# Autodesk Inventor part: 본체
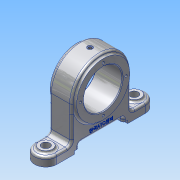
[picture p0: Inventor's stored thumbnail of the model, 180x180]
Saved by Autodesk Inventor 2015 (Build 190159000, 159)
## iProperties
Created: 2019-05
Part Number: 본체
Material: 알루미늄 6061
Document SubType Name: Modeling
Designer: user
Density: 2.7 g/cm^3
Appearance: 알루미늄 - 평지
Mass: 456.014 g
Surface Area: 318.798 cm^2
Volume: 168.894 cm^3
Author: user
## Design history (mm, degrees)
sketch "스케치1" dims "d1" = 80, "d3" = 62
  geometry: L1 (-30, 0)-(110, 0) reference; L2 (50, -40)-(2, -40); L3 (2, -40)-(2, -75); L4 (2, -75)-(-10, -75); L5 (-10, -75)-(-10, -36); L6 (0, -30)-(0, 0); L7 (0, -30)-(-6, -30); L8 (-6, -30)-(-6, -36); L9 (-6, -36)-(-10, -36); L10 (2, 40)-(2, 75); L11 (2, 75)-(-10, 75); L12 (-10, 75)-(-10, 36); L13 (-6, 30)-(-6, 36); L14 (-6, 36)-(-10, 36); L15 (0, 30)-(0, 0); L16 (0, 30)-(-6, 30); L17 (50, 40)-(2, 40); C1 r 26 at (50, 0); A1 r 40 centre (50, 0) between (50, 40) and (50, -40); 4 further points
  constraints: 32 end point, 8 symmetric about line, 4 coincident, 4 horizontal, 3 perpendicular, 2 centre point, 2 horizontal alignment, 2 point on circle, 2 vertical alignment, 1 vertical, 6 other
  dimensions: "d2" = 52 diameter of C1; "d4" = 72 diameter of L9 L1; "d5" = 60 diameter of L7 L1; "d6" = 150 diameter of L4 L1; "d8" = 60 distance from line of L5 point (50, 0); "d9" = 100 dimension on L5 (derived); "d10" = 4 distance of L8.end L5.end; "d11" = 10 distance between parallel lines of L5 L6; "d18" = 12 distance between parallel lines of L5 L3
extrude "돌출1" new body sketch "스케치1" stored distance "d19" = 30; taper "d20" = 0 deg
fillet "모깎기1" dims "d21" = 15
sketch "스케치2"
  geometry: L1 (30, 0)-(30, -20) reference; L2 (0, 0)-(30, 0) reference; L3 (0, -20)-(0, 0) reference; L4 (0, 80)-(0, 100) reference; L5 (0, 80)-(30, 80) reference; L6 (30, 100)-(30, 80) reference; C1 r 9 at (15, -20); A1 r 15 centre (15, -20) between (0, -20) and (30, -20) reference; A2 r 15 centre (15, 100) between (30, 100) and (0, 100) reference; 1 further point
  constraints: 1 centre point, 1 coincident
  dimensions: "d22" = 18 diameter of C1
extrude "돌출2" join sketch "스케치2" distance "d23" = 3; taper "d24" = 0 deg
sketch "스케치3"
  geometry: C1 r 9 at (0, 0) reference; 1 further point
hole "구멍1" sketch "스케치3" at (0, 0) diameter "d25" = 11; stored, may be unused: countersink angle "d29" = 90 deg, drill point angle "d31" = 118 deg; dims "d26" = 6, "d27" = 4, "d28" = 2, "d30" = 8
sketch "스케치4"
  geometry: C1 r 26 at (0, 50) reference; C2 r 36 at (0, 50); 1 further point
  constraints: 1 centre point, 1 coincident
  dimensions: "d32" = 72 diameter of C2
extrude "돌출3" join sketch "스케치4" distance "d33" = 3; taper "d34" = 0 deg
sketch "스케치5"
  geometry: C1 r 26 at (0, 0) reference; C2 r 26 at (0, 0) reference; 2 further points
  constraints: 1 vertical alignment
  dimensions: "d35" = 31 distance of C1.centre point (0, 31)
hole "구멍2" sketch "스케치5" at (0, 31) diameter "d36" = 3.242; stored, may be unused: countersink angle "d40" = 90 deg, drill point angle "d42" = 118 deg; dims "d37" = 6, "d38" = 7, "d39" = 1, "d41" = 8
node "작업 평면1"
sketch "스케치6"
  geometry: 1 further point
hole "구멍3" sketch "스케치6" at (0, 0) diameter "d46" = 4.917; stored, may be unused: countersink angle "d50" = 90 deg, drill point angle "d52" = 118 deg; dims "d47" = 8, "d48" = 7, "d49" = 1, "d51" = 10
node "작업 평면2"
sketch "스케치8"
  geometry: L1 (-30, 0)-(30, 0) reference; 2 further points
  constraints: 1 vertical alignment, 1 other
  dimensions: "d54" = 7 distance from line of L1 point (0, 7)
fillet "모깎기2" dims "d55" = 3
fillet "모깎기3" dims "d56" = 3
fillet "모깎기4" dims "d57" = 3
fillet "모깎기5" dims "d58" = 3
fillet "모깎기6" dims "d59" = 6
fillet "모깎기7" dims "d60" = 6
fillet "모깎기8" dims "d61" = 3
fillet "모깎기9" dims "d62" = 3
fillet "모깎기10" dims "d63" = 3
chamfer "모따기1" distance "d64" = 1; stored, may be unused: second distance "d65" = 2, angle "d66" = 45 deg
sketch "스케치9"
  geometry: C1 r 1 at (0, 0); 1 further point
  constraints: 1 centre point, 1 coincident
  dimensions: "d67" = 2 diameter of C1
extrude "돌출4" cut sketch "스케치9" stored distance "d68" = 3; taper "d69" = 0 deg
feature "엠보싱1" dims "d70" = 0.5, "d71" = 0
sketch "스케치10"
  geometry: C1 r 1.5 at (0, 26); C2 r 1.621 at (0, 31) reference; 2 further points
  constraints: 2 vertical alignment, 1 centre point, 1 other
  dimensions: "d73" = 3 diameter of C1
extrude "돌출5" cut sketch "스케치10" stored distance "d74" = 3; taper "d75" = 0 deg
node "솔리드1"
mirror "대칭1"
pattern_circular "원형 패턴1" dims angle "d44" = 360 deg
mirror "대칭2"
mirror "대칭3"
mirror "대칭4"
node "투영된 루프1"
node "투영된 루프2"
node "투영된 루프3"
other parameters: "d53" = 44
